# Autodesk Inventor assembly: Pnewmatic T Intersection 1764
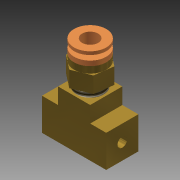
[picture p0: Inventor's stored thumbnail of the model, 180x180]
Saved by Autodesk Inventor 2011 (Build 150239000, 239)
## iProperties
Created: 2010-02
Part Number: Pnewmatic T Intersection 1764
Document SubType Name: Assembly
Designer: jgehrig
Author: jgehrig
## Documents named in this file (3)
- R:\CAD Archives\Pneumatics\Pnewmatics T Intersection 1764\Pneumatic T Intersection 1764.iam
- R:\CAD Archives\Pneumatics\Pnewmatics T Intersection 1764\Pneumatics T Intersection 1764.ipt
- R:\CAD Archives\Pneumatics\Pnewmatics T Intersection 1764\Pnewmatic Screw 1764\Pneumatic Screw 1764.iam
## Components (2 placed, 2 different names)
1. Pneumatics T Intersection 1764:1 — Mate:1, Mate:2
2. Pneumatic Screw 1764:1 [sub-assembly] — Mate:1, Mate:2
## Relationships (2: Mate 2)
- Mate:1: Pneumatics T Intersection 1764:1 ↔ Pneumatic Screw 1764:1
- Mate:2: Pneumatics T Intersection 1764:1 ↔ Pneumatic Screw 1764:1
